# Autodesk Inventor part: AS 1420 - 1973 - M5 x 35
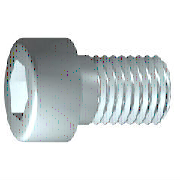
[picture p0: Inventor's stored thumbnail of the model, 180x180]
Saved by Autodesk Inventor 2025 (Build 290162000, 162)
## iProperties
Created: 2024-01
Part Number: AS 1420 - 1973 - M5 x 35
Material: Acciaio, Dolce
Description: Viti con esagono incassato metriche ISO
Document SubType Name: Modeling
Standard: AS 1420 - 1973
Designer: 18907419
Standards Organization: AS
Language: it-IT
Size Designation: M5 x 35
Categories: <MemberInstance><Categories><Category DisplayName="Elementi di fissaggio" InternalName="e4da775c-781d-43d5-af7c-5136215cf5a6" Mnemonic="FSTN"><Category DisplayN
Density: 7.85 g/cm^3
Appearance: Semilucidato
Author: 18907419
IsCustomPart: 0
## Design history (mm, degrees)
body "Solid1"
workplane "Work Plane1"
fillet "Fillet2" dims "d30" = 0.1 (= R)
revolve "Corpo" stored, may be unused: angle "d10" = 90 deg
sketch "Schizzo2"
  geometry: L1 (0, -5.95)-(0, 5.95) reference; L2 (-5.95, 0)-(5.95, 0) reference; L3 (2.309, 0)-(1.155, -2); L4 (1.155, -2)-(-1.155, -2); L5 (-1.155, -2)-(-2.309, 0); L6 (-2.309, 0)-(-1.155, 2); L7 (-1.155, 2)-(1.155, 2); L8 (1.155, 2)-(2.309, 0); 2 further points
  constraints: 12 end point, 1 coincident, 1 horizontal alignment, 1 point on line, 12 other
extrude "Intaglio" join sketch "Schizzo2" stored distance "d11" = 10; taper "d12" = 0 deg
fillet "Raccordo1" dims "d17" = 0.5 (= RR)
feature "Filettatura" dims "d13" = 16 (= GEL), "d14" = 0
chamfer "Smusso1" distance "d15" = 0.49076 (= -0.5 x SPD + 0.5 x GD); stored, may be unused: second distance "d16" = 0.49076 (= GUL), angle "d27" = 45 deg
sketch "Schizzo1"
  geometry: L1 (-1.167, 0)-(35, 0); L2 (35, 0)-(35, 2.5); L3 (35, 2.5)-(19, 2.5); L4 (19, 2.5)-(18.509, 2.5); L5 (18.509, 2.5)-(0, 2.5); L6 (0, 2.5)-(0, 4.25); L7 (0, 4.25)-(-5, 4.25); L8 (-5, 4.25)-(-5, 2.309); L9 (-5, 2.309)-(-2.5, 2.309); L10 (-2.5, 2.309)-(-1.167, 0); L11 (-13, 0)-(43, 0) reference; L12 (0, -0.85)-(0, 5.1) reference; L13 (19, 2.5)-(0, 2.5)
  constraints: 22 end point, 6 parallel, 2 collinear, 2 perpendicular, 1 horizontal, 1 point on line
  dimensions: "d1" = 16 distance from line of L3.end L2 (= GEL); "d2" = 0.49086 distance of L4.end L3.end (computed from GAL); "d3" = 5 distance between parallel lines of L8 L6 (= KOH); "d4" = 2.5 distance of L8.end L9.end (= INTI); "d5" = 60 deg angle of L10 L1; "d6" = 5 diameter of L3 L1 (= GD); "d7" = 5 diameter of L5 L1 (= BDM); "d8" = 4.6188 diameter of L9 L1 (= 1.1547 x SW); "d9" = 8.5 diameter of L7 L1 (= KOD); "d26" = 35 distance between parallel lines of L12 L2 (= NLG)
other parameters: "GD" = 5 (= NND) [user parameter; used in 2 equation terms], "NLG" = 35 [user parameter; used in 1 equation term], "GEL" = 16 [user parameter; used in 2 equation terms], "KOD" = 8.5 [user parameter; used in 1 equation term], "KOH" = 5 (= NND) [user parameter; used in 1 equation term], "INTI" = 2.5 [user parameter; used in 1 equation term], "GAL" = 0.49076 (= 0.61345 x PTC) [user parameter; used in 1 equation term], "GUL" = 0.49076 (= 0.61345 x PTC) [user parameter; used in 1 equation term], "BDM" = 5 (= NND) [user parameter; used in 1 equation term], "SW" = 4 [user parameter; used in 2 equation terms], "RR" = 0.5 (= 0.1 x NND) [user parameter; used in 1 equation term], "SPD" = 4.01848 (= NND - 1.2269 x PTC) [user parameter; used in 1 equation term], "d19" = 0, "d28" = 0, "d29" = 0, "R" = 0.1 [user parameter; used in 1 equation term], "PHH" = 0.13 [user parameter], "GD1" = 4.01848 (= THREADDIA - 1.2269 x PTC) [user parameter], "THREADDIA" = 5 [user parameter; used in 1 equation term], "FAWI" = 45 deg [user parameter], "TPU" = 12.5 (computed from PTC) [user parameter], "PTC" = 0.8 [user parameter; used in 5 equation terms], "KOH1" = 4.5 [user parameter], "NND" = 5 [user parameter; used in 5 equation terms], "TOA" = 30 deg [user parameter], "E0" = 4.62 (= 1.155 x SW) [user parameter]
